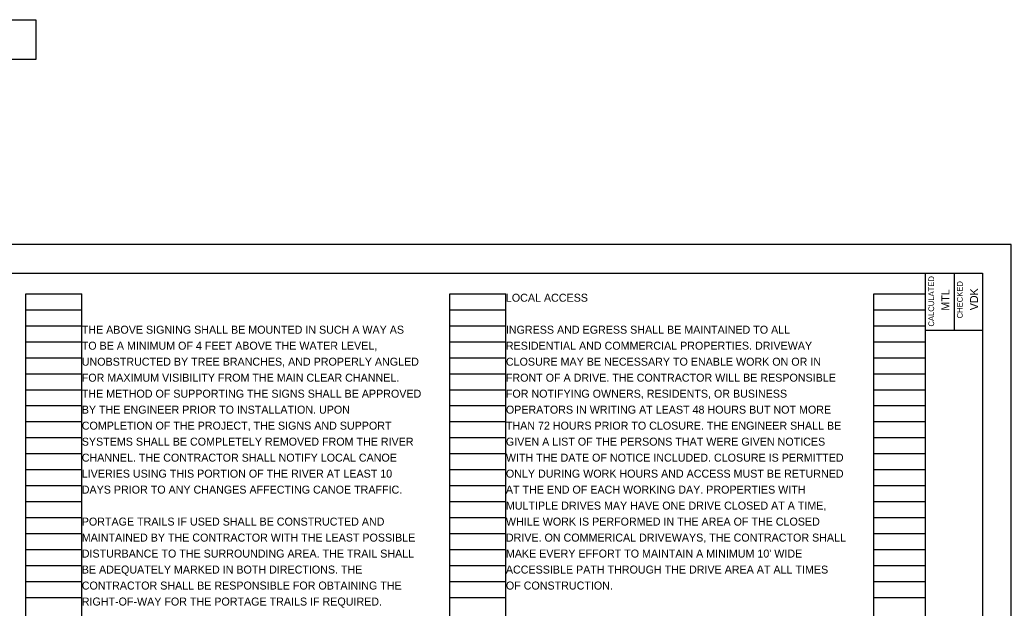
# Model space of a CAD drawing. Extents: x 0 to 34, y 0 to 27.5.
# Drawn here: x 16.66 to 34, y 15.63 to 25.94 of the extents above; entities that cross this region are included whole.
import ezdxf

# ---------------------------------------------------------------- set-up
doc = ezdxf.new("R2010")
doc.units = 0
for name, color, linetype in [('SC_Scratch1', 7, 'Continuous'), ('SH_Border', 7, 'Continuous'), ('SH_Cut_Line', 7, 'Continuous'), ('SH_Data', 7, 'Continuous'), ('SH_Text', 7, 'Continuous')]:
    doc.layers.add(name, color=color, linetype=linetype)

msp = doc.modelspace()

# ---------------------------------------------------------------- linework, layer by layer
at = {"layer": 'SC_Scratch1'}
for p, q in [((16.76, 0.98), (16.76, 21.14)), ((16.76, 21.14), (17.74, 21.14)), ((17.74, 0.98), (17.74, 21.14)), ((24.18, 0.98), (24.18, 21.14)), ((24.18, 21.14), (25.16, 21.14)), ((25.16, 0.98), (25.16, 21.14)), ((31.6, 0.98), (31.6, 21.14)), ((31.6, 21.14), (32.5, 21.14)), ((32.5, 0.98), (32.5, 21.14)), ((16.76, 20.86), (17.74, 20.86)), ((24.18, 20.86), (25.16, 20.86)), ((31.6, 20.86), (32.5, 20.86)), ((16.76, 20.58), (17.74, 20.58)), ((24.18, 20.58), (25.16, 20.58)), ((31.6, 20.58), (32.5, 20.58)), ((16.76, 20.3), (17.74, 20.3)), ((24.18, 20.3), (25.16, 20.3)), ((31.6, 20.3), (32.5, 20.3)), ((16.76, 20.02), (17.74, 20.02)), ((24.18, 20.02), (25.16, 20.02)), ((31.6, 20.02), (32.5, 20.02)), ((16.76, 19.74), (17.74, 19.74)), ((24.18, 19.74), (25.16, 19.74)), ((31.6, 19.74), (32.5, 19.74)), ((16.76, 19.46), (17.74, 19.46)), ((24.18, 19.46), (25.16, 19.46)), ((31.6, 19.46), (32.5, 19.46)), ((16.76, 19.18), (17.74, 19.18)), ((24.18, 19.18), (25.16, 19.18)), ((31.6, 19.18), (32.5, 19.18)), ((16.76, 18.9), (17.74, 18.9)), ((24.18, 18.9), (25.16, 18.9)), ((31.6, 18.9), (32.5, 18.9)), ((16.76, 18.62), (17.74, 18.62)), ((24.18, 18.62), (25.16, 18.62)), ((31.6, 18.62), (32.5, 18.62)), ((16.76, 18.34), (17.74, 18.34)), ((24.18, 18.34), (25.16, 18.34)), ((31.6, 18.34), (32.5, 18.34)), ((16.76, 18.06), (17.74, 18.06)), ((24.18, 18.06), (25.16, 18.06)), ((31.6, 18.06), (32.5, 18.06)), ((16.76, 17.78), (17.74, 17.78)), ((24.18, 17.78), (25.16, 17.78)), ((31.6, 17.78), (32.5, 17.78)), ((16.76, 17.5), (17.74, 17.5)), ((24.18, 17.5), (25.16, 17.5)), ((31.6, 17.5), (32.5, 17.5)), ((16.76, 17.22), (17.74, 17.22)), ((24.18, 17.22), (25.16, 17.22)), ((31.6, 17.22), (32.5, 17.22)), ((16.76, 16.94), (17.74, 16.94)), ((24.18, 16.94), (25.16, 16.94)), ((31.6, 16.94), (32.5, 16.94)), ((16.76, 16.66), (17.74, 16.66)), ((24.18, 16.66), (25.16, 16.66)), ((31.6, 16.66), (32.5, 16.66)), ((16.76, 16.38), (17.74, 16.38)), ((24.18, 16.38), (25.16, 16.38)), ((31.6, 16.38), (32.5, 16.38)), ((16.76, 16.1), (17.74, 16.1)), ((24.18, 16.1), (25.16, 16.1)), ((31.6, 16.1), (32.5, 16.1)), ((16.76, 15.82), (17.74, 15.82)), ((24.18, 15.82), (25.16, 15.82)), ((31.6, 15.82), (32.5, 15.82))]:
    msp.add_line(p, q, dxfattribs=at)
msp.add_lwpolyline([(10.041, 25.936), (16.938, 25.936), (16.938, 25.24), (10.041, 25.24)], close=True, dxfattribs=at)
at = {"layer": 'SH_Border'}
for p, q in [((32.5, 0.5), (32.5, 21.5)), ((33, 21.5), (33, 20.5)), ((32.5, 20.5), (33.5, 20.5))]:
    msp.add_line(p, q, dxfattribs=at)
msp.add_lwpolyline([(2, 21.5), (33.5, 21.5), (33.5, 0.5), (2, 0.5)], close=True, dxfattribs=at)
at = {"layer": 'SH_Cut_Line'}
msp.add_lwpolyline([(0, 0), (34, 0), (34, 22), (0, 22)], close=True, dxfattribs=at)

# ---------------------------------------------------------------- texts
at = {"layer": 'SH_Data'}
for s, height, p in [('CALCULATED', 0.1, (32.652, 20.565)), ('CHECKED', 0.1, (33.152, 20.708)), ('MTL', 0.14, (32.92, 20.844)), ('VDK', 0.14, (33.42, 20.851))]:
    msp.add_text(s, height=height, rotation=90, dxfattribs=at).set_placement(p)
at = {"layer": 'SH_Text'}
for s, p in [('LOCAL ACCESS', (25.16, 21)), ('THE ABOVE SIGNING SHALL BE MOUNTED IN SUCH A WAY AS ', (17.74, 20.44)), ('INGRESS AND EGRESS SHALL BE MAINTAINED TO ALL ', (25.16, 20.44)), ('TO BE A MINIMUM OF 4 FEET ABOVE THE WATER LEVEL, ', (17.74, 20.16)), ('RESIDENTIAL AND COMMERCIAL PROPERTIES. DRIVEWAY ', (25.16, 20.16)), ('UNOBSTRUCTED BY TREE BRANCHES, AND PROPERLY ANGLED ', (17.74, 19.88)), ('CLOSURE MAY BE NECESSARY TO ENABLE WORK ON OR IN ', (25.16, 19.88)), ('FOR MAXIMUM VISIBILITY FROM THE MAIN CLEAR CHANNEL. ', (17.74, 19.6)), ('FRONT OF A DRIVE. THE CONTRACTOR WILL BE RESPONSIBLE ', (25.16, 19.6)), ('THE METHOD OF SUPPORTING THE SIGNS SHALL BE APPROVED ', (17.74, 19.32)), ('FOR NOTIFYING OWNERS, RESIDENTS, OR BUSINESS ', (25.16, 19.32)), ('BY THE ENGINEER PRIOR TO INSTALLATION. UPON ', (17.74, 19.04)), ('OPERATORS IN WRITING AT LEAST 48 HOURS BUT NOT MORE ', (25.16, 19.04)), ('COMPLETION OF THE PROJECT, THE SIGNS AND SUPPORT ', (17.74, 18.76)), ('THAN 72 HOURS PRIOR TO CLOSURE. THE ENGINEER SHALL BE ', (25.16, 18.76)), ('SYSTEMS SHALL BE COMPLETELY REMOVED FROM THE RIVER ', (17.74, 18.48)), ('GIVEN A LIST OF THE PERSONS THAT WERE GIVEN NOTICES ', (25.16, 18.48)), ('CHANNEL. THE CONTRACTOR SHALL NOTIFY LOCAL CANOE ', (17.74, 18.2)), ('WITH THE DATE OF NOTICE INCLUDED. CLOSURE IS PERMITTED ', (25.16, 18.2)), ('LIVERIES USING THIS PORTION OF THE RIVER AT LEAST 10 ', (17.74, 17.92)), ('ONLY DURING WORK HOURS AND ACCESS MUST BE RETURNED ', (25.16, 17.92)), ('DAYS PRIOR TO ANY CHANGES AFFECTING CANOE TRAFFIC.', (17.74, 17.64)), ('AT THE END OF EACH WORKING DAY. PROPERTIES WITH ', (25.16, 17.64)), ('MULTIPLE DRIVES MAY HAVE ONE DRIVE CLOSED AT A TIME, ', (25.16, 17.36)), ('PORTAGE TRAILS IF USED SHALL BE CONSTRUCTED AND ', (17.74, 17.08)), ('WHILE WORK IS PERFORMED IN THE AREA OF THE CLOSED ', (25.16, 17.08)), ('MAINTAINED BY THE CONTRACTOR WITH THE LEAST POSSIBLE ', (17.74, 16.8)), ('DRIVE. ON COMMERICAL DRIVEWAYS, THE CONTRACTOR SHALL ', (25.16, 16.8)), ('DISTURBANCE TO THE SURROUNDING AREA. THE TRAIL SHALL ', (17.74, 16.52)), ("MAKE EVERY EFFORT TO MAINTAIN A MINIMUM 10' WIDE ", (25.16, 16.52)), ('BE ADEQUATELY MARKED IN BOTH DIRECTIONS. THE ', (17.74, 16.24)), ('ACCESSIBLE PATH THROUGH THE DRIVE AREA AT ALL TIMES ', (25.16, 16.24)), ('CONTRACTOR SHALL BE RESPONSIBLE FOR OBTAINING THE ', (17.74, 15.96)), ('OF CONSTRUCTION.', (25.16, 15.96)), ('RIGHT-OF-WAY FOR THE PORTAGE TRAILS IF REQUIRED.', (17.74, 15.68))]:
    msp.add_text(s, height=0.14, dxfattribs=at).set_placement(p)

doc.saveas('drawing.dxf')
